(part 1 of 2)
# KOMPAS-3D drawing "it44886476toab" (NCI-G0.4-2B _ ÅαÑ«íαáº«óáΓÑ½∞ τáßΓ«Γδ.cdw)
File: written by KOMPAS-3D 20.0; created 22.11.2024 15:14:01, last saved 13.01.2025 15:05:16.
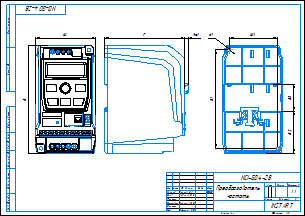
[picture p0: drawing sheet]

Sheet 1: A3, landscape

Document properties: Автор: admin; Полное имя файла: C:\Уралов Работа\Уралов (локальная)\ПЧ\! Китай 3Д-модель NCI\NCI 0.75-2.2 4B\NCI 0.75-2.2 4B.m3d

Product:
- Part/product: it44886476toab
    Масса: 2.32322
  - Body: Тело 17
      Масса: 0.0117014
  - Body: Тело 374
      Масса: 5.48304e-05
  - Body: Тело 265
      Масса: 1.32696e-05
  - Body: Тело 266
      Масса: 1.7366e-05
  - Body: Тело 267
      Масса: 1.7366e-05
  - Body: Тело 103
      Масса: 1.32696e-05
  - Body: Тело 573
      Масса: 4.06595e-05
  - Body: Тело 348
      Масса: 1.32696e-05
  - Body: Тело 270
      Масса: 1.7366e-05
  - Body: Тело 77
      Масса: 1.32696e-05
  - Body: Тело 244
      Масса: 1.65581e-05
  - Body: Тело 536
      Масса: 0.000158536
  - Body: Тело 377
      Масса: 1.65581e-05
  - Body: Тело 272
      Масса: 1.7366e-05
  - Body: Тело 273
      Масса: 5.48304e-05
  - Body: Тело 238
      Масса: 1.7366e-05
  - Body: Тело 274
      Масса: 1.7366e-05
  - Body: Тело 277
      Масса: 1.7366e-05
  - Body: Тело 530
      Масса: 5.61948e-05
  - Body: Тело 278
      Масса: 1.7366e-05
  - Body: Тело 282
      Масса: 1.7366e-05
  - Body: Тело 477
      Масса: 1.51773e-05
  - Body: Тело 526
      Масса: 5.61948e-05
  - Body: Тело 391
      Масса: 1.32696e-05
  - Body: Тело 285
      Масса: 5.48304e-05
  - Body: Тело 287
      Масса: 1.32696e-05
  - Body: Тело 290
      Масса: 0.000413213
  - Body: Тело 269
      Масса: 5.48304e-05
  - Body: Тело 292
      Масса: 1.7366e-05
  - Body: Тело 33
      Масса: 0.00516019
  - Body: Тело 252
      Масса: 5.48304e-05
  - Body: Тело 294
      Масса: 0.000413213
  - Body: Тело 297
      Масса: 3.64631e-05
  - Body: Тело 299
      Масса: 3.64028e-05
  - Body: Тело 283
      Масса: 1.7366e-05
  - Body: Тело 300
      Масса: 1.65581e-05
  - Body: Тело 303
      Масса: 1.65581e-05
  - Body: Тело 516
      Масса: 0.00507377
  - Body: Тело 384
      Масса: 5.48304e-05
  - Body: Тело 360
      Масса: 1.32696e-05
  - Body: Тело 347
      Масса: 1.32696e-05
  - Body: Тело 304
      Масса: 1.65581e-05
  - Body: Тело 307
      Масса: 0.000213463
  - Body: Тело 308
      Масса: 0.000413213
  - Body: Тело 180
      Масса: 1.32696e-05
  - Body: Тело 240
      Масса: 1.7366e-05
  - Body: Тело 309
      Масса: 1.32696e-05
  - Body: Тело 473
      Масса: 0.00425494
  - Body: Тело 311
      Масса: 5.48304e-05
  - Body: Тело 122
      Масса: 1.65581e-05
  - Body: Тело 560
      Масса: 1.65581e-05
  - Body: Тело 312
      Масса: 5.48304e-05
  - Body: Тело 317
      Масса: 1.32696e-05
  - Body: Тело 318
      Масса: 1.32696e-05
  - Body: Тело 321
      Масса: 1.32696e-05
  - Body: Тело 324
      Масса: 1.32696e-05
  - Body: Тело 480
      Масса: 1.51773e-05
  - Body: Тело 288
      Масса: 1.7366e-05
  - Body: Тело 293
      Масса: 5.48304e-05
  - Body: Тело 325
      Масса: 1.32696e-05
  - Body: Тело 99
      Масса: 1.65581e-05
  - Body: Тело 617
      Масса: 1.63919e-05
  - Body: Тело 327
      Масса: 1.32696e-05
  - Body: Тело 31
      Масса: 0.0078835
  - Body: Тело 100
      Масса: 1.65581e-05
  - Body: Тело 105
      Масса: 1.32696e-05
  - Body: Тело 328
      Масса: 1.7366e-05
  - Body: Тело 301
      Масса: 1.65581e-05
  - Body: Тело 331
      Масса: 1.7366e-05
  - Body: Тело 332
      Масса: 1.7366e-05
  - Body: Тело 446
      Масса: 0.000307437
  - Body: Тело 337
      Масса: 1.7366e-05
  - Body: Тело 338
      Масса: 1.7366e-05
  - Body: Тело 570
      Масса: 4.06595e-05
  - Body: Тело 340
      Масса: 1.32696e-05
  - Body: Тело 196
      Масса: 1.32696e-05
  - Body: Тело 357
      Масса: 1.65581e-05
  - Body: Тело 346
      Масса: 1.32696e-05
  - Body: Тело 335
      Масса: 1.32696e-05
  - Body: Тело 281
      Масса: 1.32696e-05
  - Body: Тело 362
      Масса: 1.32696e-05
  - Body: Тело 353
      Масса: 1.7366e-05
  - Body: Тело 355
      Масса: 5.48304e-05
  - Body: Тело 466
      Масса: 0.00829114
  - Body: Тело 358
      Масса: 5.48304e-05
  - Body: Тело 359
      Масса: 1.7366e-05
  - Body: Тело 286
      Масса: 1.7366e-05
  - Body: Тело 86
      Масса: 1.32696e-05
  - Body: Тело 310
      Масса: 1.7366e-05
  - Body: Тело 368
      Масса: 1.32696e-05
  - Body: Тело 370
      Масса: 1.32696e-05
  - Body: Тело 333
      Масса: 1.32696e-05
  - Body: Тело 628
      Масса: 1.51773e-05
  - Body: Тело 371
      Масса: 1.7366e-05
  - Body: Тело 75
      Масса: 1.32696e-05
  - Body: Тело 373
      Масса: 1.32696e-05
  - Body: Тело 375
      Масса: 1.32696e-05
  - Body: Тело 351
      Масса: 2.90876e-05
  - Body: Тело 76
      Масса: 1.65581e-05
  - Body: Тело 259
      Масса: 1.7366e-05
  - Body: Тело 378
      Масса: 0.000413213
  - Body: Тело 95
      Масса: 0.000935996
  - Body: Тело 372
      Масса: 1.7366e-05
  - Body: Тело 322
      Масса: 1.32696e-05
  - Body: Тело 380
      Масса: 1.32696e-05
  - Body: Тело 639
      Масса: 1.63919e-05
  - Body: Тело 385
      Масса: 1.32696e-05
  - Body: Тело 291
      Масса: 0.000213463
  - Body: Тело 386
      Масса: 1.32696e-05
  - Body: Тело 229
      Масса: 1.32696e-05
  - Body: Тело 388
      Масса: 1.32696e-05
  - Body: Тело 389
      Масса: 1.65581e-05
  - Body: Тело 93
      Масса: 3.83377e-05
  - Body: Тело 390
      Масса: 1.65581e-05
  - Body: Тело 143
      Масса: 1.32696e-05
  - Body: Тело 394
      Масса: 1.32696e-05
  - Body: Тело 395
      Масса: 1.32696e-05
  - Body: Тело 354
      Масса: 0.000213463
  - Body: Тело 396
      Масса: 1.7366e-05
  - Body: Тело 397
      Масса: 1.32696e-05
  - Body: Тело 398
      Масса: 1.65581e-05
  - Body: Тело 479
      Масса: 1.51773e-05
  - Body: Тело 402
      Масса: 1.7366e-05
  - Body: Тело 59
      Масса: 1.32696e-05
  - Body: Тело 339
      Масса: 1.32696e-05
  - Body: Тело 404
      Масса: 1.32696e-05
  - Body: Тело 89
      Масса: 0.00142218
  - Body: Тело 406
      Масса: 1.65581e-05
  - Body: Тело 393
      Масса: 1.32696e-05
  - Body: Тело 52
      Масса: 1.32696e-05
  - Body: Тело 407
      Масса: 5.48304e-05
  - Body: Тело 97
      Масса: 0.0015961
  - Body: Тело 410
      Масса: 5.48304e-05
  - Body: Тело 636
      Масса: 1.65581e-05
  - Body: Тело 412
      Масса: 1.7366e-05
  - Body: Тело 413
      Масса: 1.32696e-05
  - Body: Тело 414
      Масса: 1.32696e-05
  - Body: Тело 537
      Масса: 0.000158536
  - Body: Тело 415
      Масса: 1.7366e-05
  - Body: Тело 235
      Масса: 1.7366e-05
  - Body: Тело 419
      Масса: 1.32696e-05
  - Body: Тело 648
      Масса: 0.00426189
  - Body: Тело 420
      Масса: 1.7366e-05
  - Body: Тело 186
      Масса: 1.32696e-05
  - Body: Тело 422
      Масса: 5.48304e-05
  - Body: Тело 381
      Масса: 1.7366e-05
  - Body: Тело 423
      Масса: 1.32696e-05
  - Body: Тело 424
      Масса: 1.7366e-05
  - Body: Тело 98
      Масса: 1.65581e-05
  - Body: Тело 305
      Масса: 1.65581e-05
  - Body: Тело 425
      Масса: 1.32696e-05
  - Body: Тело 365
      Масса: 1.32696e-05
  - Body: Тело 271
      Масса: 1.32696e-05
  - Body: Тело 206
      Масса: 1.32696e-05
  - Body: Тело 429
      Масса: 0.146258
  - Body: Тело 334
      Масса: 1.7366e-05
  - Body: Тело 430
      Масса: 0.146258
  - Body: Тело 350
      Масса: 1.7366e-05
  - Body: Тело 345
      Масса: 1.32696e-05
  - Body: Тело 431
      Масса: 0.146258
  - Body: Тело 364
      Масса: 1.32696e-05
  - Body: Тело 329
      Масса: 1.32696e-05
  - Body: Тело 434
      Масса: 0.000355433
  - Body: Тело 5
      Масса: 0.000355433
  - Body: Тело 124
      Масса: 1.65581e-05
  - Body: Тело 344
      Масса: 1.32696e-05
  - Body: Тело 436
      Масса: 0.000355433
  - Body: Тело 439
      Масса: 0.00113358
  - Body: Тело 606
      Масса: 0.000137594
  - Body: Тело 323
      Масса: 1.32696e-05
  - Body: Тело 441
      Масса: 0.00113358
  - Body: Тело 442
      Масса: 0.000355433
  - Body: Тело 554
      Масса: 4.06595e-05
  - Body: Тело 444
      Масса: 0.000355433
  - Body: Тело 246
      Масса: 1.65581e-05
  - Body: Тело 445
      Масса: 0.00113358
  - Body: Тело 438
      Масса: 0.000355433
  - Body: Тело 106
      Масса: 1.32696e-05
  - Body: Тело 508
      Масса: 1.51773e-05
  - Body: Тело 577
      Масса: 1.7366e-05
  - Body: Тело 392
      Масса: 1.32696e-05
  - Body: Тело 193
      Масса: 1.32696e-05
  - Body: Тело 448
      Масса: 0.000307437
  - Body: Тело 481
      Масса: 1.51773e-05
  - Body: Тело 450
      Масса: 6.34685e-05
  - Body: Тело 222
      Масса: 1.32696e-05
  - Body: Тело 315
      Масса: 1.7366e-05
  - Body: Тело 452
      Масса: 1.63919e-05
  - Body: Тело 53
      Масса: 1.32696e-05
  - Body: Тело 401
      Масса: 1.32696e-05
  - Body: Тело 418
      Масса: 1.7366e-05
  - Body: Тело 517
      Масса: 0.00106884
  - Body: Тело 417
      Масса: 1.32696e-05
  - Body: Тело 453
      Масса: 1.63919e-05
  - Body: Тело 454
      Масса: 0.000382752
  - Body: Тело 428
      Масса: 0.146258
  - Body: Тело 455
      Масса: 1.51773e-05
  - Body: Тело 539
      Масса: 1.51773e-05
  - Body: Тело 457
      Масса: 1.51773e-05
  - Body: Тело 459
      Масса: 3.90329e-05
  - Body: Тело 557
      Масса: 0.00166679
  - Body: Тело 569
      Масса: 1.32696e-05
  - Body: Тело 578
      Масса: 1.32696e-05
  - Body: Тело 626
      Масса: 1.32696e-05
  - Body: Тело 134
      Масса: 1.32696e-05
  - Body: Тело 582
      Масса: 1.65581e-05
  - Body: Тело 203
      Масса: 1.32696e-05
  - Body: Тело 572
      Масса: 1.32696e-05
  - Body: Тело 567
      Масса: 1.32696e-05
  - Body: Тело 207
      Масса: 1.32696e-05
  - Body: Тело 645
      Масса: 1.32696e-05
  - Body: Тело 559
      Масса: 1.65581e-05
  - Body: Тело 152
      Масса: 1.32696e-05
  - Body: Тело 449
      Масса: 0.0658364
  - Body: Тело 316
      Масса: 1.32696e-05
  - Body: Тело 376
      Масса: 1.32696e-05
  - Body: Тело 575
      Масса: 1.32696e-05
  - Body: Тело 576
      Масса: 1.32696e-05
  - Body: Тело 85
      Масса: 1.32696e-05
  - Body: Тело 574
      Масса: 4.06595e-05
  - Body: Тело 399
      Масса: 1.32696e-05
  - Body: Тело 320
      Масса: 1.32696e-05
  - Body: Тело 275
      Масса: 1.7366e-05
  - Body: Тело 213
      Масса: 1.32696e-05
  - Body: Тело 625
      Масса: 1.32696e-05
  - Body: Тело 644
      Масса: 0.000158536
  - Body: Тело 584
      Масса: 4.06595e-05
  - Body: Тело 70
      Масса: 1.65581e-05
  - Body: Тело 588
      Масса: 1.32696e-05
  - Body: Тело 276
      Масса: 1.7366e-05
  - Body: Тело 363
      Масса: 1.32696e-05
  - Body: Тело 474
      Масса: 1.51773e-05
  - Body: Тело 548
      Масса: 2.98222e-05
  - Body: Тело 409
      Масса: 5.48304e-05
  - Body: Тело 472
      Масса: 0.00329327
  - Body: Тело 533
      Масса: 5.61948e-05
  - Body: Тело 647
      Масса: 0.00426189
  - Body: Тело 586
      Масса: 1.32696e-05
  - Body: Тело 262
      Масса: 1.7366e-05
  - Body: Тело 562
      Масса: 0.000382752
  - Body: Тело 379
      Масса: 1.32696e-05
  - Body: Тело 632
      Масса: 1.51773e-05
  - Body: Тело 565
      Масса: 4.06595e-05
  - Body: Тело 118
      Масса: 0.000413213
  - Body: Тело 597
      Масса: 7.12116e-06
  - Body: Тело 613
      Масса: 1.63919e-05
  - Body: Тело 387
      Масса: 1.32696e-05
  - Body: Тело 593
      Масса: 1.32696e-05
  - Body: Тело 408
      Масса: 5.48304e-05
  - Body: Тело 109
      Масса: 1.32696e-05
  - Body: Тело 163
      Масса: 1.32696e-05
  - Body: Тело 488
      Масса: 1.51773e-05
  - Body: Тело 367
      Масса: 1.32696e-05
  - Body: Тело 411
      Масса: 5.48304e-05
  - Body: Тело 583
      Масса: 4.06595e-05
  - Body: Тело 598
      Масса: 7.12116e-06
  - Body: Тело 551
      Масса: 0.000255388
  - Body: Тело 405
      Масса: 1.32696e-05
  - Body: Тело 619
      Масса: 1.32696e-05
  - Body: Тело 361
      Масса: 1.32696e-05
  - Body: Тело 589
      Масса: 1.32696e-05
  - Body: Тело 499
      Масса: 1.51773e-05
  - Body: Тело 440
      Масса: 0.000355433
  - Body: Тело 640
      Масса: 1.63919e-05
  - Body: Тело 150
      Масса: 1.32696e-05
  - Body: Тело 568
      Масса: 1.32696e-05
  - Body: Тело 194
      Масса: 1.32696e-05
  - Body: Тело 251
      Масса: 1.7366e-05
  - Body: Тело 342
      Масса: 0.00166679
  - Body: Тело 604
      Масса: 5.61948e-05
  - Body: Тело 650
      Масса: 0.00426189
  - Body: Тело 161
      Масса: 1.32696e-05
  - Body: Тело 611
      Масса: 0.000158536
  - Body: Тело 210
      Масса: 1.32696e-05
  - Body: Тело 540
      Масса: 1.51773e-05
  - Body: Тело 296
      Масса: 3.6965e-05
  - Body: Тело 601
      Масса: 5.61948e-05
  - Body: Тело 484
      Масса: 0.000158536
  - Body: Тело 622
      Масса: 1.32696e-05
  - Body: Тело 527
      Масса: 0.000141095
  - Body: Тело 624
      Масса: 1.32696e-05
  - Body: Тело 121
      Масса: 0.000413213
  - Body: Тело 600
      Масса: 5.61948e-05
  - Body: Тело 603
      Масса: 5.61948e-05
  - Body: Тело 607
      Масса: 1.32696e-05
  - Body: Тело 289
      Масса: 1.7366e-05
  - Body: Тело 471
      Масса: 0.00329327
  - Body: Тело 313
      Масса: 1.7366e-05
  - Body: Тело 591
      Масса: 7.12116e-06
  - Body: Тело 356
      Масса: 1.65581e-05
  - Body: Тело 306
      Масса: 1.65581e-05
  - Body: Тело 541
      Масса: 0.000158536
  - Body: Тело 511
      Масса: 1.51773e-05
  - Body: Тело 160
      Масса: 1.32696e-05
  - Body: Тело 566
      Масса: 1.32696e-05
  - Body: Тело 563
      Масса: 4.06595e-05
  - Body: Тело 638
      Масса: 1.7366e-05
  - Body: Тело 489
      Масса: 1.51773e-05
  - Body: Тело 456
      Масса: 1.51773e-05
  - Body: Тело 485
      Масса: 0.000158536
  - Body: Тело 284
      Масса: 1.7366e-05
  - Body: Тело 138
      Масса: 2.23009e-05
  - Body: Тело 225
      Масса: 1.32696e-05
  - Body: Тело 546
      Масса: 0.000255388
  - Body: Тело 113
      Масса: 0.000413213
  - Body: Тело 642
      Масса: 3.90329e-05
  - Body: Тело 618
      Масса: 1.63919e-05
  - Body: Тело 525
      Масса: 0.000213463
  - Body: Тело 164
      Масса: 1.32696e-05
  - Body: Тело 253
      Масса: 1.7366e-05
  - Body: Тело 561
      Масса: 1.65581e-05
  - Body: Тело 594
      Масса: 1.32696e-05
  - Body: Тело 482
      Масса: 1.51773e-05
  - Body: Тело 81
      Масса: 1.32696e-05
  - Body: Тело 280
      Масса: 1.32696e-05
  - Body: Тело 494
      Масса: 1.51773e-05
  - Body: Тело 641
      Масса: 3.90329e-05
  - Body: Тело 564
      Масса: 4.06595e-05
  - Body: Тело 633
      Масса: 1.51773e-05
  - Body: Тело 518
      Масса: 0.00166679
  - Body: Тело 620
      Масса: 1.7366e-05
  - Body: Тело 497
      Масса: 1.51773e-05
  - Body: Тело 151
      Масса: 1.65581e-05
  - Body: Тело 302
      Масса: 1.65581e-05
  - Body: Тело 110
      Масса: 1.32696e-05
  - Body: Тело 646
      Масса: 0.000137594
  - Body: Тело 264
      Масса: 1.7366e-05
  - Body: Тело 635
      Масса: 1.65581e-05
  - Body: Тело 608
      Масса: 0.00166679
  - Body: Тело 460
      Масса: 3.90329e-05
  - Body: Тело 403
      Масса: 1.7366e-05
  - Body: Тело 612
      Масса: 0.000158536
  - Body: Тело 492
      Масса: 1.51773e-05
  - Body: Тело 139
      Масса: 0.000194606
  - Body: Тело 400
      Масса: 1.7366e-05
  - Body: Тело 605
      Масса: 5.61948e-05
  - Body: Тело 623
      Масса: 1.32696e-05
  - Body: Тело 117
      Масса: 0.000413213
  - Body: Тело 185
      Масса: 1.32696e-05
  - Body: Тело 631
      Масса: 1.51773e-05
  - Body: Тело 580
      Масса: 1.32696e-05
  - Body: Тело 349
      Масса: 1.7366e-05
  - Body: Тело 621
      Масса: 1.32696e-05
  - Body: Тело 627
      Масса: 0.000255388
  - Body: Тело 531
      Масса: 5.61948e-05
  - Body: Тело 649
      Масса: 0.00426189
  - Body: Тело 585
      Масса: 4.06595e-05
  - Body: Тело 236
      Масса: 1.7366e-05
  - Body: Тело 513
      Масса: 1.51773e-05
  - Body: Тело 426
      Масса: 1.32696e-05
  - Body: Тело 341
      Масса: 0.00166679
  - Body: Тело 470
      Масса: 0.00329329
  - Body: Тело 382
      Масса: 5.48304e-05
  - Body: Тело 227
      Масса: 1.32696e-05
  - Body: Тело 476
      Масса: 1.51773e-05
  - Body: Тело 538
      Масса: 1.51773e-05
  - Body: Тело 596
      Масса: 1.32696e-05
  - Body: Тело 609
      Масса: 1.7366e-05
  - Body: Тело 610
      Масса: 0.00166679
  - Body: Тело 263
      Масса: 1.7366e-05
  - Body: Тело 629
      Масса: 1.51773e-05
  - Body: Тело 336
      Масса: 3.64028e-05
  - Body: Тело 495
      Масса: 1.51773e-05
  - Body: Тело 168
      Масса: 1.32696e-05
  - Body: Тело 298
      Масса: 3.64495e-05
  - Body: Тело 279
      Масса: 1.32696e-05
  - Body: Тело 72
      Масса: 1.65581e-05
  - Body: Тело 500
      Масса: 1.51773e-05
  - Body: Тело 505
      Масса: 1.51773e-05
  - Body: Тело 558
      Масса: 0.00726683
  - Body: Тело 630
      Масса: 1.51773e-05
  - Body: Тело 602
      Масса: 5.61948e-05
  - Body: Тело 556
      Масса: 0.00166679
  - Body: Тело 555
      Масса: 0.00166679
  - Body: Тело 634
      Масса: 1.51773e-05
  - Body: Тело 435
      Масса: 0.00113358
  - Body: Тело 416
      Масса: 1.7366e-05
  - Body: Тело 190
      Масса: 1.32696e-05
  - Body: Тело 330
      Масса: 1.7366e-05
  - Body: Тело 28
      Масса: 0.00135688
  - Body: Тело 553
      Масса: 4.06595e-05
  - Body: Тело 176
      Масса: 1.32696e-05
  - Body: Тело 552
      Масса: 4.06595e-05
  - Body: Тело 534
      Масса: 1.32696e-05
  - Body: Тело 595
      Масса: 1.32696e-05
  - Body: Тело 23
      Масса: 0.0243258
  - Body: Тело 247
      Масса: 1.7366e-05
  - Body: Тело 314
      Масса: 1.7366e-05
  - Body: Тело 126
      Масса: 0.000512664
  - Body: Тело 157
      Масса: 1.32696e-05
  - Body: Тело 550
      Масса: 0.000255388
  - Body: Тело 32
      Масса: 0.0135217
  - Body: Тело 592
      Масса: 7.12116e-06
  - Body: Тело 366
      Масса: 1.7366e-05
  - Body: Тело 504
      Масса: 1.51773e-05
  - Body: Тело 258
      Масса: 1.7366e-05
  - Body: Тело 421
      Масса: 1.7366e-05
  - Body: Тело 35
      Масса: 0.262997
  - Body: Тело 204
      Масса: 1.32696e-05
  - Body: Тело 549
      Масса: 0.000255388
  - Body: Тело 257
      Масса: 1.7366e-05
  - Body: Тело 614
      Масса: 1.63919e-05
  - Body: Тело 547
      Масса: 0.000255388
  - Body: Тело 41
      Масса: 0.0119524
  - Body: Тело 71
      Масса: 1.65581e-05
  - Body: Тело 506
      Масса: 1.51773e-05
  - Body: Тело 545
      Масса: 1.51773e-05
  - Body: Тело 145
      Масса: 1.32696e-05
  - Body: Тело 461
      Масса: 0.000404362
  - Body: Тело 502
      Масса: 1.51773e-05
  - Body: Тело 352
      Масса: 2.90876e-05
  - Body: Тело 120
      Масса: 0.000413213
  - Body: Тело 295
      Масса: 1.65581e-05
  - Body: Тело 544
      Масса: 0.000158536
  - Body: Тело 469
      Масса: 0.0113891
  - Body: Тело 146
      Масса: 1.32696e-05
  - Body: Тело 149
      Масса: 1.32696e-05
  - Body: Тело 615
      Масса: 1.63919e-05
  - Body: Тело 543
      Масса: 0.000158536
  - Body: Тело 542
      Масса: 0.000158536
  - Body: Тело 462
      Масса: 0.000404362
  - Body: Тело 616
      Масса: 1.63919e-05
  - Body: Тело 343
      Масса: 0.00166679
  - Body: Тело 532
      Масса: 5.61948e-05
  - Body: Тело 493
      Масса: 1.51773e-05
  - Body: Тело 529
      Масса: 5.61948e-05
  - Body: Тело 579
      Масса: 0.00017125
  - Body: Тело 200
      Масса: 1.32696e-05
  - Body: Тело 239
      Масса: 5.48304e-05
  - Body: Тело 443
      Масса: 0.00113358
  - Body: Тело 216
      Масса: 0.000280294
  - Body: Тело 468
      Масса: 0.0253857
  - Body: Тело 64
      Масса: 1.65581e-05
  - Body: Тело 528
      Масса: 0.000141095
  - Body: Тело 599
      Масса: 7.12116e-06
  - Body: Тело 590
      Масса: 1.32696e-05
  - Body: Тело 191
      Масса: 1.32696e-05
  - Body: Тело 523
      Масса: 0.000255388
  - Body: Тело 458
      Масса: 1.51773e-05
  - Body: Тело 319
      Масса: 1.32696e-05
  - Body: Тело 49
      Масса: 0.00944
  - Body: Тело 522
      Масса: 1.65581e-05
  - Body: Тело 521
      Масса: 1.32696e-05
  - Body: Тело 571
      Масса: 0.00166679
  - Body: Тело 509
      Масса: 1.51773e-05
  - Body: Тело 326
      Масса: 1.32696e-05
  - Body: Тело 520
      Масса: 5.48304e-05
  - Body: Тело 427
      Масса: 1.32696e-05
  - Body: Тело 519
      Масса: 1.7366e-05
  - Body: Тело 637
      Масса: 1.51773e-05
  - Body: Тело 524
      Масса: 1.65581e-05
  - Body: Тело 432
      Масса: 0.000118347
  - Body: Тело 487
      Масса: 1.65581e-05
  - Body: Тело 510
      Масса: 1.51773e-05
  - Body: Тело 515
      Масса: 0.00507372
  - Body: Тело 512
      Масса: 1.51773e-05
  - Body: Тело 155
      Масса: 1.32696e-05
  - Body: Тело 587
      Масса: 1.32696e-05
  - Body: Тело 174
      Масса: 1.65581e-05
  - Body: Тело 507
      Масса: 1.51773e-05
  - Body: Тело 12
      Масса: 0.000703761
  - Body: Тело 187
      Масса: 1.32696e-05
  - Body: Тело 447
      Масса: 0.000307437
  - Body: Тело 503
      Масса: 1.51773e-05
  - Body: Тело 501
      Масса: 1.51773e-05
  - Body: Тело 369
      Масса: 1.32696e-05
  - Body: Тело 60
      Масса: 1.32696e-05
  - Body: Тело 498
      Масса: 1.51773e-05
  - Body: Тело 535
      Масса: 1.52051e-05
  - Body: Тело 437
      Масса: 0.00113358
  - Body: Тело 496
      Масса: 1.51773e-05
  - Body: Тело 433
      Масса: 0.000118347
  - Body: Тело 491
      Масса: 1.65581e-05
  - Body: Тело 490
      Масса: 1.51773e-05
  - Body: Тело 581
      Масса: 1.65581e-05
  - Body: Тело 486
      Масса: 0.000158536
  - Body: Тело 483
      Масса: 1.51773e-05
  - Body: Тело 514
      Масса: 1.51773e-05
  - Body: Тело 643
      Масса: 0.000158536
  - Body: Тело 125
      Масса: 1.65581e-05
  - Body: Тело 383
      Масса: 0.000340816
  - Body: Тело 465
      Масса: 0.00829114
  - Body: Тело 478
      Масса: 1.51773e-05
  - Body: Тело 451
      Масса: 6.34685e-05
  - Body: Тело 475
      Масса: 1.51773e-05
  - Body: Тело 467
      Масса: 0.00436982
  - Body: Тело 268
      Масса: 5.48304e-05
  - Body: Тело 464
      Масса: 0.00829425
  - Body: Тело 226
      Масса: 0.000413213
  - Body: Тело 463
      Масса: 0.000404362
  - Body: Тело 170
      Масса: 1.32696e-05
  - Body: Тело 261
      Масса: 3.83377e-05
  - Body: Тело 260
      Масса: 1.7366e-05
  - Body: Тело 167
      Масса: 1.32696e-05
  - Body: Тело 256
      Масса: 1.7366e-05
  - Body: Тело 119
      Масса: 0.000413213
  - Body: Тело 255
      Масса: 1.7366e-05
  - Body: Тело 254
      Масса: 1.32696e-05
  - Body: Тело 250
      Масса: 1.7366e-05
  - Body: Тело 249
      Масса: 1.7366e-05
  - Body: Тело 248
      Масса: 1.7366e-05
  - Body: Тело 19
      Масса: 0.0117014
  - Body: Тело 114
      Масса: 0.000413213
  - Body: Тело 234
      Масса: 1.7366e-05
  - Body: Тело 245
      Масса: 1.65581e-05
  - Body: Тело 243
      Масса: 1.65581e-05
  - Body: Тело 242
      Масса: 1.65581e-05
  - Body: Тело 65
      Масса: 1.65581e-05
  - Body: Тело 241
      Масса: 0.000424983
  - Body: Тело 141
      Масса: 0.000213463
  - Body: Тело 237
      Масса: 1.7366e-05
  - Body: Тело 1
      Масса: 0.00113358
  - Body: Тело 233
      Масса: 1.7366e-05
  - Body: Тело 232
      Масса: 5.48304e-05
  - Body: Тело 231
      Масса: 0.00398049
  - Body: Тело 230
      Масса: 1.32696e-05
  - Body: Тело 184
      Масса: 1.32696e-05
  - Body: Тело 228
      Масса: 1.32696e-05
  - Body: Тело 224
      Масса: 1.32696e-05
  - Body: Тело 162
      Масса: 1.65581e-05
  - Body: Тело 223
      Масса: 1.32696e-05
  - Body: Тело 221
      Масса: 1.65581e-05
  - Body: Тело 220
      Масса: 1.32696e-05
  - Body: Тело 219
      Масса: 1.32696e-05
  - Body: Тело 218
      Масса: 1.32696e-05
  - Body: Тело 217
      Масса: 1.32696e-05
  - Body: Тело 215
      Масса: 1.65581e-05
  - Body: Тело 9
      Масса: 0.000703761
  - Body: Тело 214
      Масса: 1.32696e-05
  - Body: Тело 212
      Масса: 1.32696e-05
  - Body: Тело 211
      Масса: 1.32696e-05
  - Body: Тело 209
      Масса: 1.32696e-05
  - Body: Тело 208
      Масса: 1.7366e-05
  - Body: Тело 205
      Масса: 1.32696e-05
  - Body: Тело 202
      Масса: 1.32696e-05
  - Body: Тело 201
      Масса: 1.32696e-05
  - Body: Тело 29
      Масса: 0.00135688
  - Body: Тело 199
      Масса: 1.32696e-05
  - Body: Тело 198
      Масса: 1.32696e-05
  - Body: Тело 197
      Масса: 1.32696e-05
  - Body: Тело 195
      Масса: 1.32696e-05
  - Body: Тело 192
      Масса: 1.32696e-05
  - Body: Тело 189
      Масса: 1.32696e-05
  - Body: Тело 188
      Масса: 1.32696e-05
  - Body: Тело 183
      Масса: 1.32696e-05
  - Body: Тело 182
      Масса: 1.32696e-05
  - Body: Тело 181
      Масса: 1.32696e-05
  - Body: Тело 179
      Масса: 1.32696e-05
  - Body: Тело 178
      Масса: 1.32696e-05
  - Body: Тело 44
      Масса: 0.0119524
  - Body: Тело 50
      Масса: 0.00101975
  - Body: Тело 177
      Масса: 1.32696e-05
  - Body: Тело 175
      Масса: 1.32696e-05
  - Body: Тело 45
      Масса: 0.0267013
  - Body: Тело 137
      Масса: 1.32696e-05
  - Body: Тело 173
      Масса: 1.32696e-05
  - Body: Тело 172
      Масса: 1.65581e-05
  - Body: Тело 153
      Масса: 1.32696e-05
  - Body: Тело 171
      Масса: 1.32696e-05
  - Body: Тело 169
      Масса: 1.32696e-05
  - Body: Тело 140
      Масса: 0.000213463
  - Body: Тело 166
      Масса: 1.32696e-05
  - Body: Тело 165
      Масса: 1.65581e-05
  - Body: Тело 159
      Масса: 1.32696e-05
  - Body: Тело 116
      Масса: 0.000413213
  - Body: Тело 158
      Масса: 1.32696e-05
  - Body: Тело 156
      Масса: 1.32696e-05
  - Body: Тело 154
      Масса: 1.32696e-05
  - Body: Тело 148
      Масса: 1.32696e-05
  - Body: Тело 147
      Масса: 1.32696e-05
  - Body: Тело 24
      Масса: 0.0110484
  - Body: Тело 62
      Масса: 1.32696e-05
  - Body: Тело 144
      Масса: 1.32696e-05
  - Body: Тело 142
      Масса: 0.000213463
  - Body: Тело 136
      Масса: 1.32696e-05
  - Body: Тело 135
      Масса: 1.32696e-05
  - Body: Тело 38
      Масса: 0.00631989
  - Body: Тело 133
      Масса: 1.32696e-05
  - Body: Тело 132
      Масса: 1.32696e-05
  - Body: Тело 131
      Масса: 1.32696e-05
  - Body: Тело 16
      Масса: 0.000703761
  - Body: Тело 130
      Масса: 1.32696e-05
  - Body: Тело 112
      Масса: 0.000413213
  - Body: Тело 129
      Масса: 1.32696e-05
  - Body: Тело 128
      Масса: 1.32696e-05
  - Body: Тело 127
      Масса: 1.32696e-05
  - Body: Тело 123
      Масса: 1.65581e-05
  - Body: Тело 115
      Масса: 0.000413213
  - Body: Тело 111
      Масса: 0.000194606
  - Body: Тело 108
      Масса: 1.32696e-05
  - Body: Тело 107
      Масса: 1.32696e-05
  - Body: Тело 104
      Масса: 1.32696e-05
  - Body: Тело 102
      Масса: 1.32696e-05
  - Body: Тело 90
      Масса: 0.000966482
  - Body: Тело 101
      Масса: 1.32696e-05
  - Body: Тело 96
      Масса: 0.00181049
  - Body: Тело 94
      Масса: 0.00554276
  - Body: Тело 92
      Масса: 3.83377e-05
  - Body: Тело 91
      Масса: 0.0246688
  - Body: Тело 15
      Масса: 0.000703761
  - Body: Тело 88
      Масса: 0.000873873
  - Body: Тело 87
      Масса: 0.000966482
  - Body: Тело 84
      Масса: 1.32696e-05
  - Body: Тело 83
      Масса: 1.32696e-05
  - Body: Тело 82
      Масса: 1.32696e-05
  - Body: Тело 80
      Масса: 1.32696e-05
  - Body: Тело 79
      Масса: 1.32696e-05
  - Body: Тело 78
      Масса: 1.65581e-05
  - Body: Тело 74
      Масса: 1.65581e-05
  - Body: Тело 48
      Масса: 0.00853877
  - Body: Тело 73
      Масса: 1.65581e-05
  - Body: Тело 69
      Масса: 1.65581e-05
  - Body: Тело 68
      Масса: 1.65581e-05
  - Body: Тело 67
      Масса: 1.65581e-05
  - Body: Тело 66
      Масса: 1.65581e-05
  - Body: Тело 63
      Масса: 1.65581e-05
  - Body: Тело 57
      Масса: 1.32696e-05
  - Body: Тело 61
      Масса: 1.32696e-05
  - Body: Тело 58
      Масса: 1.32696e-05
  - Body: Тело 56
      Масса: 1.32696e-05
  - Body: Тело 55
      Масса: 1.32696e-05
  - Body: Тело 54
      Масса: 1.32696e-05
  - Body: Тело 51
      Масса: 1.32696e-05
  - Body: Тело 47
      Масса: 0.551587
  - Body: Тело 46
      Масса: 0.0119034
  - Body: Тело 43
      Масса: 0.0119524
  - Body: Тело 42
      Масса: 0.0119524
  - Body: Тело 40
      Масса: 0.0119524
  - Body: Тело 39
      Масса: 0.0119524
  - Body: Тело 37
      Масса: 0.0343584
  - Body: Тело 36
      Масса: 0.0668131
  - Body: Тело 34
      Масса: 0.00831628
  - Body: Тело 30
      Масса: 0.000935996
  - Body: Тело 27
      Масса: 0.00135688
  - Body: Тело 26
      Масса: 0.00135688
  - Body: Тело 25
      Масса: 0.00135688
  - Body: Тело 22
      Масса: 0.0636504
  - Body: Тело 21
      Масса: 0.0864411
  - Body: Тело 20
      Масса: 0.120334
  - Body: Тело 18
      Масса: 0.0117014
  - Body: Тело 14
      Масса: 0.000703761
  - Body: Тело 13
      Масса: 0.000703761
  - Body: Тело 11
      Масса: 0.000703761
  - Body: Тело 10
      Масса: 0.0160396
  - Body: Тело 8
      Масса: 0.000703761
  - Body: Тело 7
      Масса: 0.000703761
  - Body: Тело 6
      Масса: 0.000355433
  - Body: Тело 4
      Масса: 0.000355433
  - Body: Тело 3
      Масса: 0.00113358
  - Body: Тело 2
      Масса: 0.00113358

Title block, sheet 1: Наименование: Преобразователь / частоты; designation: NCI-G0.4-2B; Количество листов документа: 1; organisation: INSTART; cell 10: Согласовано; Форматы листов документа: A3; stored path: P:\INSTART\Технический отдел\ОР\Прочие задачи\КД на номенклатурный ряд\КД на типоразмеры ПЧ\NCI\NCI-G0.75_P1.5-4B\NCI-G0.75_P1.5-4B _ Преобразователь частоты.cdw; Разработал: Уралов Д.А.; Проверил: Андреев Н.В.; Подписал: Смелков Ж.Е.; Утвердил: Ефремов И.Н.; Разработал, date: 13.01.25

Views: Вид 1
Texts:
  Кривая без истории:10000
  Кривая без истории:10001
  Кривая без истории:10002
  Кривая без истории:10003
  Кривая без истории:10004
  Кривая без истории:10005
  Кривая без истории:10006
  Кривая без истории:10007
  Кривая без истории:10008
  Кривая без истории:10009
  Кривая без истории:10010
  Кривая без истории:10011
  Кривая без истории:10012
  Кривая без истории:10013
  Кривая без истории:10014
  Кривая без истории:10015
  Кривая без истории:10016
  Кривая без истории:10017
  Кривая без истории:10018
  Кривая без истории:10019
  Кривая без истории:10020
  Кривая без истории:10021
  Кривая без истории:10022
  Кривая без истории:10023
  Кривая без истории:10024
  Кривая без истории:10025
  Кривая без истории:10026
  Кривая без истории:10027
  Кривая без истории:10028
  Кривая без истории:10029
  Кривая без истории:10030
  Кривая без истории:10031
  Кривая без истории:10032
  Кривая без истории:10033
  Кривая без истории:10034
  Кривая без истории:10035
  Кривая без истории:10036
  Кривая без истории:10037
  Кривая без истории:10038
  Кривая без истории:10039
  Кривая без истории:10040
  Кривая без истории:10041
  Кривая без истории:10042
  Кривая без истории:10043
  Кривая без истории:10044
  Кривая без истории:10045
  Кривая без истории:10046
  Кривая без истории:10047
  Кривая без истории:10048
  Кривая без истории:10049
  Кривая без истории:10050
  Кривая без истории:10051
  Кривая без истории:10052
  Кривая без истории:10053
  Кривая без истории:10054
  Кривая без истории:10055
  Кривая без истории:10056
  Кривая без истории:10057
  Кривая без истории:10058
  Кривая без истории:10059
  Кривая без истории:10060
  Кривая без истории:10061
  Кривая без истории:10062
  Кривая без истории:10063
  Кривая без истории:10064
  Кривая без истории:10065
  Кривая без истории:10066
  Кривая без истории:10067
  Кривая без истории:10068
  Кривая без истории:10069
  Кривая без истории:10070
  Кривая без истории:10071
  Кривая без истории:10072
  Кривая без истории:10073
  Кривая без истории:10074
  Кривая без истории:10075
  Кривая без истории:10076
  Кривая без истории:10077
  Кривая без истории:10078
  Кривая без истории:10079
  Кривая без истории:10080
  Кривая без истории:10081
  Кривая без истории:10082
  Кривая без истории:10083
  Кривая без истории:10084
  Кривая без истории:10085
  Кривая без истории:10086
  Кривая без истории:10087
  Кривая без истории:10088
  Кривая без истории:10089
  Кривая без истории:10090
  Кривая без истории:10091
  Кривая без истории:10092
  Кривая без истории:10093
  Кривая без истории:10094
  Кривая без истории:10095
  Кривая без истории:10096
  Кривая без истории:10097
  Кривая без истории:10098
  Кривая без истории:10099
  Кривая без истории:10100
  Кривая без истории:10101
  Кривая без истории:10102
  Кривая без истории:10103
  Кривая без истории:10104
  Кривая без истории:10105
  Кривая без истории:10106
  Кривая без истории:10107
  Кривая без истории:10108
  Кривая без истории:10109
  Кривая без истории:10110
  Кривая без истории:10111
  Кривая без истории:10112
  Кривая без истории:10113
  Кривая без истории:10114
  Кривая без истории:10115
  Кривая без истории:10116
  Кривая без истории:10117
  Кривая без истории:10118
  Кривая без истории:10119
  Кривая без истории:10120
  Кривая без истории:10121
  Кривая без истории:10122
  Кривая без истории:10123
  Кривая без истории:10124
  Кривая без истории:10125
  Кривая без истории:10126
  Кривая без истории:10127
  Кривая без истории:10128
  Кривая без истории:10129
  Кривая без истории:10130
  Кривая без истории:10131
  Кривая без истории:10132
  Кривая без истории:10133
  Кривая без истории:10134
  Кривая без истории:10135
  Кривая без истории:10136
  Кривая без истории:10137
  Кривая без истории:10138
  Кривая без истории:10139
  Кривая без истории:10140
  Кривая без истории:10141
  Кривая без истории:10142
  Кривая без истории:10143
  Кривая без истории:10144
  Кривая без истории:10145
  Кривая без истории:10146
  Кривая без истории:10147
  Кривая без истории:10148
  Кривая без истории:10149
  Кривая без истории:10150
  Кривая без истории:10151
  Кривая без истории:10152
  Кривая без истории:10153
  Кривая без истории:10154
  Кривая без истории:10155
  Кривая без истории:10156
  Кривая без истории:10157
  Кривая без истории:10158
  Кривая без истории:10159
  Кривая без истории:10160
  Кривая без истории:10161
  Кривая без истории:10162
  Кривая без истории:10163
  Кривая без истории:10164
  Кривая без истории:10165
  Кривая без истории:10166
  Кривая без истории:10167
  Кривая без истории:10168
  Кривая без истории:10169
  Кривая без истории:10170
  Кривая без истории:10171
  Кривая без истории:10172
  Кривая без истории:10173
  Кривая без истории:10174
  Кривая без истории:10175
  Кривая без истории:10176
  Кривая без истории:10177
  Кривая без истории:10178
  Кривая без истории:10179
  Кривая без истории:10180
  Кривая без истории:10181
  Кривая без истории:10182
  Кривая без истории:10183
  Кривая без истории:10184
  Кривая без истории:10185
  Кривая без истории:10186
  Кривая без истории:10187
  Кривая без истории:10188
  Кривая без истории:10189
  Кривая без истории:10190
  Кривая без истории:10191
  Кривая без истории:10192
  Кривая без истории:10193
  Кривая без истории:10194
  Кривая без истории:10195
  Кривая без истории:10196
  Кривая без истории:10197
  Кривая без истории:10198
  Кривая без истории:10199
  Кривая без истории:10200
  Кривая без истории:10201
  Кривая без истории:10202
  Кривая без истории:10203
  Кривая без истории:10204
  Кривая без истории:10205
  Кривая без истории:10206
  Кривая без истории:10207
  Кривая без истории:10208
  Кривая без истории:10209
  Кривая без истории:10210
  Кривая без истории:10211
  Кривая без истории:10212
  Кривая без истории:10213
  Кривая без истории:10214
  Кривая без истории:10215
  Кривая без истории:10216
  Кривая без истории:10217
  Кривая без истории:10218
  Кривая без истории:10219
  Кривая без истории:10220
  Кривая без истории:10221
  Кривая без истории:10222
  Кривая без истории:10223
  Кривая без истории:10224
  Кривая без истории:10225
  Кривая без истории:10226
  Кривая без истории:10227
  Кривая без истории:10228
  Кривая без истории:10229
  Кривая без истории:10230
  Кривая без истории:10231
  Кривая без истории:10232
  Кривая без истории:10233
  Кривая без истории:10234
  Кривая без истории:10235
  Кривая без истории:10236
  Кривая без истории:10237
  Кривая без истории:10238
  Кривая без истории:10239
  Кривая без истории:10240
  Кривая без истории:10241
  Кривая без истории:10242
  Кривая без истории:10243
  Кривая без истории:10244
  Кривая без истории:10245
  Кривая без истории:10246
  Кривая без истории:10247
  Кривая без истории:10248
  Кривая без истории:10249
  Кривая без истории:10250
  Кривая без истории:10251
  Кривая без истории:10252
  Кривая без истории:10253
  Кривая без истории:10254
  Кривая без истории:10255
  Кривая без истории:10256
  Кривая без истории:10257
  Кривая без истории:10258
  Кривая без истории:10259
  Кривая без истории:10260
  Кривая без истории:10261
  Кривая без истории:10262
  Кривая без истории:10263
  Кривая без истории:10264
  Кривая без истории:10265
  Кривая без истории:10266
  Кривая без истории:10267
  Кривая без истории:10268
  Кривая без истории:10269
  Кривая без истории:10270
  Кривая без истории:10271
  Кривая без истории:10272
  Кривая без истории:10273
  Кривая без истории:10274
  Кривая без истории:10275
  Кривая без истории:10276
  Кривая без истории:10277
  Кривая без истории:10278
  Кривая без истории:10279
  Кривая без истории:10280
  Кривая без истории:10281
  Кривая без истории:10282
  Кривая без истории:10283
  Кривая без истории:10284
  Кривая без истории:10285
  Кривая без истории:10286
  Кривая без истории:10287
  Кривая без истории:10288
  Кривая без истории:10289
  Кривая без истории:10290
  Кривая без истории:10291
  Кривая без истории:10292
  Кривая без истории:10293
  Кривая без истории:10294
  Кривая без истории:10295
  Кривая без истории:10296
  Кривая без истории:10297
  Кривая без истории:10298
  Кривая без истории:10299
  Кривая без истории:10300
  Кривая без истории:10301
  Кривая без истории:10302
  Кривая без истории:10303
  Кривая без истории:10304
  Кривая без истории:10305
  Кривая без истории:10306
  Кривая без истории:10307
  Кривая без истории:10308
  Кривая без истории:10309
  Кривая без истории:10310
  Кривая без истории:10311
  Кривая без истории:10312
  Кривая без истории:10313
  Кривая без истории:10314
  Кривая без истории:10315
  Кривая без истории:10316
  Кривая без истории:10317
  Кривая без истории:10318
  Кривая без истории:10319
  Кривая без истории:10320
  Кривая без истории:10321
  Кривая без истории:10322
  Кривая без истории:10323
  Кривая без истории:10324
  Кривая без истории:10325
  Кривая без истории:10326
  Кривая без истории:10327
  Кривая без истории:10328
  Кривая без истории:10329
  Кривая без истории:10330
  Кривая без истории:10331
  Кривая без истории:10332
  Кривая без истории:10333
  Кривая без истории:10334
  Кривая без истории:10335
  Кривая без истории:10336
  Кривая без истории:10337
  Кривая без истории:10338
  Кривая без истории:10339
  Кривая без истории:10340
  Кривая без истории:10341
  Кривая без истории:10342
  Кривая без истории:10343
  Кривая без истории:10344
  Кривая без истории:10345
  Кривая без истории:10346
  Кривая без истории:10347
  Кривая без истории:10348
  Кривая без истории:10349
  Кривая без истории:10350
  Кривая без истории:10351
  Кривая без истории:10352
  Кривая без истории:10353
  Кривая без истории:10354
  Кривая без истории:10355
  Кривая без истории:10356
  Кривая без истории:10357
  Кривая без истории:10358
  Кривая без истории:10359
  Кривая без истории:10360
  Кривая без истории:10361
  Кривая без истории:10362
  Кривая без истории:10363
  Кривая без истории:10364
  Кривая без истории:10365
  Кривая без истории:10366
  Кривая без истории:10367
  Кривая без истории:10368
  Кривая без истории:10369
  Кривая без истории:10370
  Кривая без истории:10371
  Кривая без истории:10372
  Кривая без истории:10373
  Кривая без истории:10374
  Кривая без истории:10375
  Кривая без истории:10376
  Кривая без истории:10377
  Кривая без истории:10378
  Кривая без истории:10379
  Кривая без истории:10380
  Кривая без истории:10381
  Кривая без истории:10382
  Кривая без истории:10383
  Кривая без истории:10384
  Кривая без истории:10385
  Кривая без истории:10386
  Кривая без истории:10387
  Кривая без истории:10388
  Кривая без истории:10389
  Кривая без истории:10390
  Кривая без истории:10391
  Кривая без истории:10392
  Кривая без истории:10393
  Кривая без истории:10394
  Кривая без истории:10395
  Кривая без истории:10396
  Кривая без истории:10397
  Кривая без истории:10398
  Кривая без истории:10399
  Кривая без истории:10400
  Кривая без истории:10401
  Кривая без истории:10402
  Кривая без истории:10403
  Кривая без истории:10404
  Кривая без истории:10405
  Кривая без истории:10406
  Кривая без истории:10407
  Кривая без истории:10408
  Кривая без истории:10409
  Кривая без истории:10410
  Кривая без истории:10411
  Кривая без истории:10412
  Кривая без истории:10413
  Кривая без истории:10414
  Кривая без истории:10415
  Кривая без истории:10416
  Кривая без истории:10417
  Кривая без истории:10418
  Кривая без истории:10419
  Кривая без истории:10420
  Кривая без истории:10421
  Кривая без истории:10422
  Кривая без истории:10423
  Кривая без истории:10424
  Кривая без истории:10425
  Кривая без истории:10426
  Кривая без истории:10427
  Кривая без истории:10428
  Кривая без истории:10429
  Кривая без истории:10430
  Кривая без истории:10431
  Кривая без истории:10432
  Кривая без истории:10433
  Кривая без истории:10434
  Кривая без истории:10435
  Кривая без истории:10436
  Кривая без истории:10437
  Кривая без истории:10438
  Кривая без истории:10439
  Кривая без истории:10440
  Кривая без истории:10441
  Кривая без истории:10442
  Кривая без истории:10443
  Кривая без истории:10444
  Кривая без истории:10445
  Кривая без истории:10446
  Кривая без истории:10447
  Кривая без истории:10448
  Кривая без истории:10449
  Кривая без истории:10450
  Кривая без истории:10451
  Кривая без истории:10452
  Кривая без истории:10453
  Кривая без истории:10454
  Кривая без истории:10455
  Кривая без истории:10456
  Кривая без истории:10457
  Кривая без истории:10458
  Кривая без истории:10459
  Кривая без истории:10460
  Кривая без истории:10461
  Кривая без истории:10462
  Кривая без истории:10463
  Кривая без истории:10464
  Кривая без истории:10465
  Кривая без истории:10466
  Кривая без истории:10467
  Кривая без истории:10468
  Кривая без истории:10469
  Кривая без истории:10470
  Кривая без истории:10471
  Кривая без истории:10472
  Кривая без истории:10473
  Кривая без истории:10474
  Кривая без истории:10475
  Кривая без истории:10476
  Кривая без истории:10477
  Кривая без истории:10478
  Кривая без истории:10479
  Кривая без истории:10480
  Кривая без истории:10481
  Кривая без истории:10482
  Кривая без истории:10483
  Кривая без истории:10484
  Кривая без истории:10485
  Кривая без истории:10486
  Кривая без истории:10487
  Кривая без истории:10488
  Кривая без истории:10489
  Кривая без истории:10490
  Кривая без истории:10491
  Кривая без истории:10492
  Кривая без истории:10493
  Кривая без истории:10494
  Кривая без истории:10495
  Кривая без истории:10496
  Кривая без истории:10497
  Кривая без истории:10498
  Кривая без истории:10499
  Кривая без истории:10500
  Кривая без истории:10501
  Кривая без истории:10502
  Кривая без истории:10503
  Кривая без истории:10504
  Кривая без истории:10505
  Кривая без истории:10506
  Кривая без истории:10507
  Кривая без истории:10508
  Кривая без истории:10509
  Кривая без истории:10510
  Кривая без истории:10511
  Кривая без истории:10512
  Кривая без истории:10513
  Кривая без истории:10514
  Кривая без истории:10515
  Кривая без истории:10516
  Кривая без истории:10517
  Кривая без истории:10518
  Кривая без истории:10519
  Кривая без истории:10520
  Кривая без истории:10521
  Кривая без истории:10522
  Кривая без истории:10523
  Кривая без истории:10524
  Кривая без истории:10525
  Кривая без истории:10526
  Кривая без истории:10527
  Кривая без истории:10528
  Кривая без истории:10529
  Кривая без истории:10530
  Кривая без истории:10531
  Кривая без истории:10532
  Кривая без истории:10533
  Кривая без истории:10534
  Кривая без истории:10535
  Кривая без истории:10536
  Кривая без истории:10537
  Кривая без истории:10538
  Кривая без истории:10539
  Кривая без истории:10540
  Кривая без истории:10541
  Кривая без истории:10542
  Кривая без истории:10543
  Кривая без истории:10544
  Кривая без истории:10545
  Кривая без истории:10546
  Кривая без истории:10547
  Кривая без истории:10548
  Кривая без истории:10549
  Кривая без истории:10550
  Кривая без истории:10551
  Кривая без истории:10552
  Кривая без истории:10553
  Кривая без истории:10554
  Кривая без истории:10555
  Кривая без истории:10556
  Кривая без истории:10557
  Кривая без истории:10558
  Кривая без истории:10559
  Кривая без истории:10560
  Кривая без истории:10561
  Кривая без истории:10562
  Кривая без истории:10563
  Кривая без истории:10564
  Кривая без истории:10565
  Кривая без истории:10566
  Кривая без истории:10567
  Кривая без истории:10568
  Кривая без истории:10569
  Кривая без истории:10570
  Кривая без истории:10571
  Кривая без истории:10572
  Кривая без истории:10573
  Кривая без истории:10574
  Кривая без истории:10575
  Кривая без истории:10576
  Кривая без истории:10577
  Кривая без истории:10578
  Кривая без истории:10579
  Кривая без истории:10580
  Кривая без истории:10581
  Кривая без истории:10582
  Кривая без истории:10583
  Кривая без истории:10584
  Кривая без истории:10585
  Кривая без истории:10586
  Кривая без истории:10587
  Кривая без истории:10588
  Кривая без истории:10589
  Кривая без истории:10590
  Кривая без истории:10591
  Кривая без истории:10592
  Кривая без истории:10593
  Кривая без истории:10594
  Кривая без истории:10595
  Кривая без истории:10596
  Кривая без истории:10597
  Кривая без истории:10598
  Кривая без истории:10599
  Кривая без истории:10600
  Кривая без истории:10601
  Кривая без истории:10602
  Кривая без истории:10603
  Кривая без истории:10604
  Кривая без истории:10605
  Кривая без истории:10606
  Кривая без истории:10607
  Кривая без истории:10608
  Кривая без истории:10609
  Кривая без истории:10610
  Кривая без истории:10611
  Кривая без истории:10612
  Кривая без истории:10613
  Кривая без истории:10614
  Кривая без истории:10615
  Кривая без истории:10616
  Кривая без истории:10617
  Кривая без истории:10618
  Кривая без истории:10619
  Кривая без истории:10620
  Кривая без истории:10621
  Кривая без истории:10622
  Кривая без истории:10623
  Кривая без истории:10624
  Кривая без истории:10625
  Кривая без истории:10626
  Кривая без истории:10627
  Кривая без истории:10628
  Кривая без истории:10629
  Кривая без истории:10630
  Кривая без истории:10631
  Кривая без истории:10632
  Кривая без истории:10633
  Кривая без истории:10634
  Кривая без истории:10635
  Кривая без истории:10636
  Кривая без истории:10637
  Кривая без истории:10638
  Кривая без истории:10639
  Кривая без истории:10640
  Кривая без истории:10641
  Кривая без истории:10642
  Кривая без истории:10643
  Кривая без истории:10644
  Кривая без истории:10645
  Кривая без истории:10646
  Кривая без истории:10647
  Кривая без истории:10648
  Кривая без истории:10649
  Кривая без истории:10650
  Кривая без истории:10651
  Кривая без истории:10652
  Кривая без истории:10653
  Кривая без истории:10654
  Кривая без истории:10655
  Кривая без истории:10656
  Кривая без истории:10657
  Кривая без истории:10658
  Кривая без истории:10659
  Кривая без истории:10660
  Кривая без истории:10661
  Кривая без истории:10662
  Кривая без истории:10663
  Кривая без истории:10664
  Кривая без истории:10665
  Кривая без истории:10666
  Кривая без истории:10667
  Кривая без истории:10668
  Кривая без истории:10669
  Кривая без истории:10670
  Кривая без истории:10671
  Кривая без истории:10672
  Кривая без истории:10673
  Кривая без истории:10674
  Кривая без истории:10675
  Кривая без истории:10676
  Кривая без истории:10677
  Кривая без истории:10678
  Кривая без истории:10679
  Кривая без истории:10680
  Кривая без истории:10681
  Кривая без истории:10682
  Кривая без истории:10683
  Кривая без истории:10684
  Кривая без истории:10685
  Кривая без истории:10686
  Кривая без истории:10687
  Кривая без истории:10688
  Кривая без истории:10689
  Кривая без истории:10690
  Кривая без истории:10691
  Кривая без истории:10692
  Кривая без истории:10693
  Кривая без истории:10694
  Кривая без истории:10695
  Кривая без истории:10696
  Кривая без истории:10697
  Кривая без истории:10698
  Кривая без истории:10699
  Кривая без истории:10700
  Кривая без истории:10701
  Кривая без истории:10702
  Кривая без истории:10703
  Кривая без истории:10704
  Кривая без истории:10705
  Кривая без истории:10706
  Кривая без истории:10707
  Кривая без истории:10708
  Кривая без истории:10709
  Кривая без истории:10710
  Кривая без истории:10711
  Кривая без истории:10712
  Кривая без истории:10713
  Кривая без истории:10714
  Кривая без истории:10715
  Кривая без истории:10716
  Кривая без истории:10717
  Кривая без истории:10718
  Кривая без истории:10719
  Кривая без истории:10720
  Кривая без истории:10721
  Кривая без истории:10722
  Кривая без истории:10723
  Кривая без истории:10724
  Кривая без истории:10725
  Кривая без истории:10726
  Кривая без истории:10727
  Кривая без истории:10728
  Кривая без истории:10729
  Кривая без истории:10730
  Кривая без истории:10731
  Кривая без истории:10732
  Кривая без истории:10733
  Кривая без истории:10734
  Кривая без истории:10735
  Кривая без истории:10736
  Кривая без истории:10737
  Кривая без истории:10738
  Кривая без истории:10739
  Кривая без истории:10740
  Кривая без истории:10741
  Кривая без истории:10742
  Кривая без истории:10743
  Кривая без истории:10744
  Кривая без истории:10745
  Кривая без истории:10746
  Кривая без истории:10747
  Кривая без истории:10748
  Кривая без истории:10749
  Кривая без истории:10750
  Кривая без истории:10751
  Кривая без истории:10752
  Кривая без истории:10753
  Кривая без истории:10754
  Кривая без истории:10755
  Кривая без истории:10756
  Кривая без истории:10757
  Кривая без истории:10758
  Кривая без истории:10759
  Кривая без истории:10760
  Кривая без истории:10761
  Кривая без истории:10762
  Кривая без истории:10763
